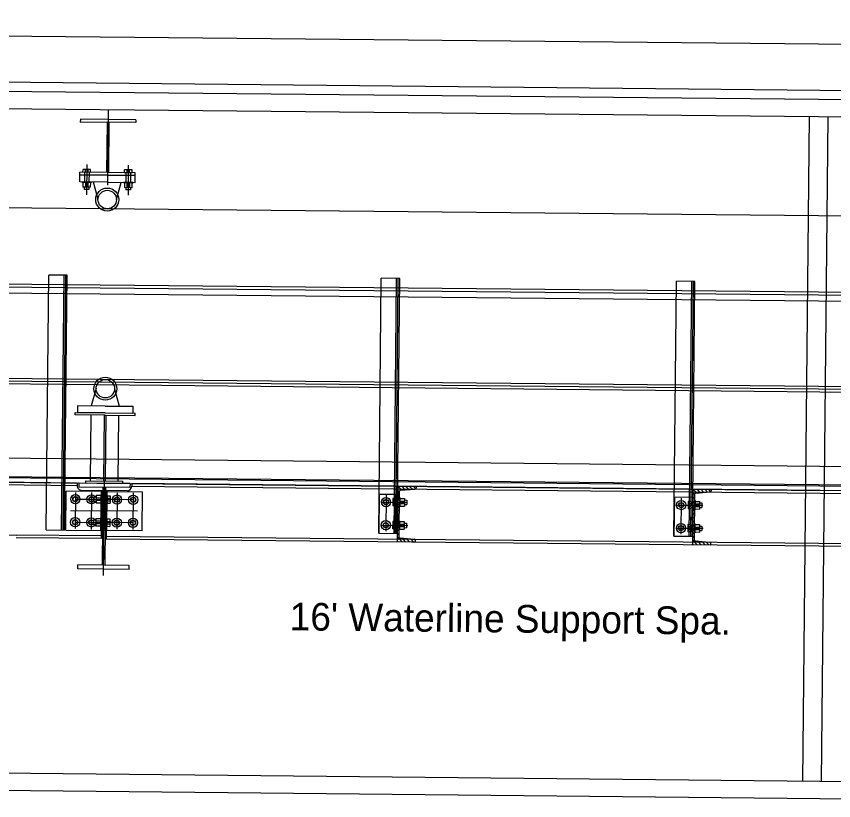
# Model space of a CAD drawing. Extents: x 632312 to 632885, y 378199 to 378534.
# Drawn here: x 632839.14 to 632853.91, y 378305.55 to 378319.72 of the extents above; entities that cross this region are included whole.
import ezdxf

# ---------------------------------------------------------------- set-up
doc = ezdxf.new("R2010")
doc.units = 0
doc.layers.add('SHT_Dimensions', color=7, linetype='Continuous')

msp = doc.modelspace()

# ---------------------------------------------------------------- linework, layer by layer
at = {"layer": 'SHT_Dimensions'}
for p, q in [((632803.483, 378319.72), (632858.169, 378319.176)), ((632803.475, 378318.886), (632858.055, 378318.344)), ((632803.473, 378318.72), (632858.195, 378318.176)), ((632803.47, 378318.407), (632858.281, 378317.862)), ((632840.801, 378318.035), (632840.788, 378316.671)), ((632853.468, 378317.91), (632853.348, 378305.911)), ((632840.3, 378317.862), (632840.299, 378317.811)), ((632841.299, 378317.801), (632840.299, 378317.811)), ((632841.3, 378317.852), (632840.3, 378317.862)), ((632840.783, 378317.807), (632840.774, 378316.899)), ((632840.815, 378317.806), (632840.806, 378316.899)), ((632841.3, 378317.852), (632841.299, 378317.801)), ((632853.801, 378317.907), (632853.681, 378305.907)), ((632840.416, 378317.042), (632840.411, 378316.495)), ((632841.166, 378317.034), (632841.161, 378316.488)), ((632841.29, 378316.894), (632840.29, 378316.904)), ((632840.29, 378316.854), (632840.29, 378316.904)), ((632840.347, 378316.903), (632840.348, 378316.955)), ((632840.483, 378316.902), (632840.347, 378316.903)), ((632840.483, 378316.954), (632840.348, 378316.955)), ((632840.373, 378316.903), (632840.372, 378316.728)), ((632840.393, 378316.903), (632840.393, 378316.955)), ((632840.438, 378316.902), (632840.438, 378316.955)), ((632840.457, 378316.902), (632840.455, 378316.727)), ((632840.483, 378316.902), (632840.483, 378316.954)), ((632841.097, 378316.896), (632841.098, 378316.948)), ((632841.233, 378316.895), (632841.097, 378316.896)), ((632841.233, 378316.947), (632841.098, 378316.948)), ((632841.123, 378316.896), (632841.122, 378316.72)), ((632841.143, 378316.895), (632841.143, 378316.948)), ((632841.188, 378316.895), (632841.188, 378316.947)), ((632841.207, 378316.895), (632841.205, 378316.719)), ((632841.233, 378316.895), (632841.233, 378316.947)), ((632841.29, 378316.844), (632841.29, 378316.894)), ((632840.288, 378316.729), (632840.29, 378316.854)), ((632840.788, 378316.724), (632840.288, 378316.729)), ((632840.79, 378316.849), (632840.29, 378316.854)), ((632841.29, 378316.844), (632840.29, 378316.854)), ((632840.79, 378316.849), (632841.29, 378316.844)), ((632841.288, 378316.719), (632841.29, 378316.844)), ((632858.298, 378316.07), (632803.452, 378316.616)), ((632840.33, 378316.728), (632840.33, 378316.718)), ((632840.497, 378316.726), (632840.33, 378316.728)), ((632840.497, 378316.716), (632840.33, 378316.718)), ((632840.346, 378316.718), (632840.345, 378316.634)), ((632840.48, 378316.633), (632840.345, 378316.634)), ((632840.371, 378316.634), (632840.37, 378316.592)), ((632840.454, 378316.591), (632840.37, 378316.592)), ((632840.391, 378316.717), (632840.39, 378316.634)), ((632840.436, 378316.717), (632840.435, 378316.633)), ((632840.454, 378316.633), (632840.454, 378316.591)), ((632840.481, 378316.716), (632840.48, 378316.633)), ((632840.497, 378316.726), (632840.497, 378316.716)), ((632840.619, 378316.413), (632840.538, 378316.726)), ((632840.788, 378316.724), (632841.288, 378316.719)), ((632840.952, 378316.409), (632841.038, 378316.721)), ((632841.08, 378316.721), (632841.08, 378316.71)), ((632841.247, 378316.719), (632841.08, 378316.721)), ((632841.247, 378316.709), (632841.08, 378316.71)), ((632841.096, 378316.71), (632841.095, 378316.627)), ((632841.23, 378316.625), (632841.095, 378316.627)), ((632841.121, 378316.626), (632841.12, 378316.585)), ((632841.204, 378316.584), (632841.12, 378316.585)), ((632841.141, 378316.71), (632841.14, 378316.626)), ((632841.186, 378316.709), (632841.185, 378316.626)), ((632841.204, 378316.626), (632841.204, 378316.584)), ((632841.231, 378316.709), (632841.23, 378316.625)), ((632841.247, 378316.719), (632841.247, 378316.709)), ((632803.438, 378315.189), (632857.879, 378314.647)), ((632803.439, 378315.241), (632857.859, 378314.7)), ((632858.496, 378314.527), (632803.437, 378315.074)), ((632839.683, 378310.443), (632839.729, 378315.046)), ((632840.062, 378315.043), (632839.729, 378315.046)), ((632839.959, 378310.44), (632840.005, 378315.044)), ((632839.99, 378310.439), (632840.036, 378315.043)), ((632840.016, 378310.439), (632840.062, 378315.043)), ((632845.69, 378310.385), (632845.736, 378314.989)), ((632846.069, 378314.986), (632845.736, 378314.989)), ((632845.966, 378310.382), (632846.012, 378314.986)), ((632845.997, 378310.382), (632846.043, 378314.986)), ((632846.023, 378310.382), (632846.069, 378314.986)), ((632851.023, 378310.332), (632851.069, 378314.936)), ((632851.402, 378314.933), (632851.069, 378314.936)), ((632851.299, 378310.329), (632851.345, 378314.933)), ((632851.33, 378310.329), (632851.376, 378314.933)), ((632851.357, 378310.329), (632851.402, 378314.933)), ((632803.421, 378313.491), (632857.782, 378312.95)), ((632857.708, 378312.993), (632803.422, 378313.532)), ((632803.421, 378313.439), (632857.788, 378312.898)), ((632840.585, 378312.996), (632840.498, 378312.685)), ((632840.918, 378312.993), (632840.998, 378312.68)), ((632840.248, 378312.687), (632840.247, 378312.562)), ((632840.748, 378312.682), (632840.248, 378312.687)), ((632840.748, 378312.682), (632841.248, 378312.677)), ((632841.248, 378312.677), (632841.247, 378312.552)), ((632840.205, 378312.521), (632840.205, 378312.562)), ((632840.205, 378312.562), (632841.289, 378312.552)), ((632840.747, 378312.515), (632840.205, 378312.521)), ((632840.747, 378312.557), (632840.247, 378312.562)), ((632840.485, 378311.33), (632840.497, 378312.518)), ((632840.722, 378311.328), (632840.734, 378312.516)), ((632840.747, 378312.557), (632841.247, 378312.552)), ((632840.759, 378312.515), (632840.747, 378311.328)), ((632840.747, 378312.515), (632841.288, 378312.51)), ((632840.985, 378311.325), (632840.996, 378312.513)), ((632841.288, 378312.51), (632841.289, 378312.552)), ((632803.407, 378312.095), (632857.654, 378311.556)), ((632803.404, 378311.762), (632857.65, 378311.222)), ((632803.404, 378311.741), (632857.65, 378311.201)), ((632803.403, 378311.657), (632853.734, 378311.157)), ((632840.241, 378311.291), (632824.315, 378311.45)), ((632840.24, 378311.243), (632824.332, 378311.401)), ((632840.241, 378311.291), (632840.24, 378311.243)), ((632840.272, 378311.291), (632840.271, 378311.218)), ((632841.197, 378311.282), (632840.272, 378311.291)), ((632840.401, 378311.29), (632840.401, 378311.331)), ((632840.401, 378311.331), (632841.068, 378311.325)), ((632840.485, 378311.33), (632840.985, 378311.325)), ((632840.718, 378309.624), (632840.735, 378311.338)), ((632841.068, 378311.283), (632841.068, 378311.325)), ((632841.197, 378311.282), (632841.196, 378311.209)), ((632857.643, 378311.118), (632841.228, 378311.281)), ((632841.228, 378311.281), (632841.228, 378311.233)), ((632840.037, 378310.439), (632840.044, 378311.147)), ((632840.711, 378311.141), (632840.044, 378311.147)), ((632840.21, 378311.123), (632840.204, 378310.468)), ((632841.196, 378311.209), (632840.271, 378311.218)), ((632840.323, 378311.159), (632840.69, 378311.155)), ((632840.502, 378311.12), (632840.495, 378310.449)), ((632840.672, 378310.433), (632840.679, 378311.141)), ((632840.681, 378310.287), (632840.69, 378311.155)), ((632840.697, 378309.809), (632840.711, 378311.214)), ((632840.703, 378310.432), (632840.711, 378311.141)), ((632840.756, 378311.214), (632840.742, 378309.809)), ((632840.748, 378310.432), (632840.755, 378311.14)), ((632840.755, 378311.14), (632841.422, 378311.134)), ((632840.776, 378311.155), (632840.767, 378310.286)), ((632841.143, 378311.151), (632840.776, 378311.155)), ((632840.779, 378310.432), (632840.786, 378311.14)), ((632841.228, 378311.233), (632857.678, 378311.07)), ((632841.415, 378310.425), (632841.422, 378311.134)), ((632846.032, 378311.234), (632846.022, 378310.234)), ((632846.062, 378311.134), (632846.031, 378311.165)), ((632846.032, 378311.234), (632846.365, 378311.23)), ((632846.101, 378311.166), (632846.034, 378311.234)), ((632846.062, 378311.144), (632846.054, 378310.323)), ((632846.067, 378311.233), (632846.067, 378311.232)), ((632846.083, 378311.164), (632846.344, 378311.183)), ((632846.167, 378311.17), (632846.105, 378311.233)), ((632846.232, 378311.175), (632846.176, 378311.232)), ((632846.298, 378311.179), (632846.247, 378311.231)), ((632846.359, 378311.188), (632846.317, 378311.231)), ((632846.365, 378311.23), (632846.365, 378311.203)), ((632851.365, 378311.181), (632851.355, 378310.181)), ((632851.365, 378311.181), (632851.698, 378311.177)), ((632851.434, 378311.113), (632851.367, 378311.181)), ((632851.4, 378311.18), (632851.4, 378311.179)), ((632851.416, 378311.111), (632851.677, 378311.13)), ((632851.5, 378311.117), (632851.438, 378311.18)), ((632851.565, 378311.122), (632851.509, 378311.179)), ((632851.631, 378311.126), (632851.58, 378311.178)), ((632851.692, 378311.135), (632851.65, 378311.178)), ((632851.698, 378311.177), (632851.698, 378311.15)), ((632840.209, 378311), (632840.501, 378310.997)), ((632840.501, 378310.997), (632840.731, 378310.995)), ((632840.543, 378311.038), (632840.542, 378310.955)), ((632840.585, 378311.038), (632840.543, 378311.038)), ((632840.585, 378311.064), (632840.583, 378310.928)), ((632840.668, 378311.018), (632840.584, 378311.019)), ((632840.667, 378310.973), (632840.584, 378310.974)), ((632840.668, 378311.063), (632840.585, 378311.064)), ((632840.668, 378311.079), (632840.667, 378310.912)), ((632840.679, 378311.078), (632840.668, 378311.079)), ((632840.679, 378311.078), (632840.677, 378310.912)), ((632840.785, 378311.036), (632840.678, 378311.037)), ((632840.962, 378310.992), (632840.731, 378310.995)), ((632840.786, 378311.062), (632840.784, 378310.926)), ((632840.785, 378311.017), (632840.837, 378311.016)), ((632840.785, 378310.972), (632840.837, 378310.971)), ((632840.786, 378311.062), (632840.838, 378311.061)), ((632840.838, 378311.061), (632840.836, 378310.926)), ((632840.963, 378311.115), (632840.957, 378310.459)), ((632841.254, 378310.989), (632840.962, 378310.992)), ((632841.255, 378311.112), (632841.248, 378310.453)), ((632845.697, 378311.093), (632845.69, 378310.385)), ((632845.697, 378311.093), (632846.031, 378311.09)), ((632845.822, 378311.069), (632845.816, 378310.421)), ((632845.946, 378311.013), (632845.945, 378310.877)), ((632845.998, 378311.012), (632845.946, 378311.013)), ((632845.992, 378310.382), (632845.999, 378311.09)), ((632845.998, 378311.012), (632845.997, 378310.877)), ((632845.998, 378310.986), (632846.06, 378310.986)), ((632846.023, 378310.382), (632846.031, 378311.09)), ((632846.06, 378310.993), (632846.03, 378311.024)), ((632846.061, 378311.064), (632846.031, 378311.095)), ((632846.061, 378311.027), (632846.059, 378310.861)), ((632846.061, 378311.027), (632846.071, 378311.027)), ((632846.071, 378311.027), (632846.069, 378310.861)), ((632846.071, 378311.012), (632846.154, 378311.011)), ((632846.154, 378311.011), (632846.153, 378310.875)), ((632846.154, 378310.985), (632846.196, 378310.984)), ((632846.196, 378310.984), (632846.195, 378310.901)), ((632851.03, 378311.04), (632851.023, 378310.332)), ((632851.03, 378311.04), (632851.364, 378311.037)), ((632851.155, 378311.016), (632851.149, 378310.368)), ((632851.325, 378310.329), (632851.332, 378311.037)), ((632851.357, 378310.329), (632851.364, 378311.037)), ((632851.393, 378310.94), (632851.363, 378310.971)), ((632851.395, 378311.081), (632851.364, 378311.112)), ((632851.394, 378311.01), (632851.364, 378311.042)), ((632851.395, 378311.091), (632851.387, 378310.27)), ((632851.394, 378310.974), (632851.392, 378310.808)), ((632851.394, 378310.974), (632851.404, 378310.974)), ((632851.404, 378310.974), (632851.403, 378310.808)), ((632840.584, 378310.954), (632840.542, 378310.955)), ((632840.667, 378310.928), (632840.583, 378310.928)), ((632840.677, 378310.912), (632840.667, 378310.912)), ((632840.785, 378310.952), (632840.677, 378310.953)), ((632840.784, 378310.926), (632840.836, 378310.926)), ((632845.737, 378310.947), (632846.212, 378310.942)), ((632845.997, 378310.877), (632845.945, 378310.877)), ((632845.998, 378310.967), (632845.946, 378310.968)), ((632845.998, 378310.922), (632845.946, 378310.923)), ((632845.997, 378310.903), (632846.059, 378310.902)), ((632846.059, 378310.851), (632846.028, 378310.883)), ((632846.06, 378310.922), (632846.029, 378310.953)), ((632846.059, 378310.861), (632846.069, 378310.861)), ((632846.07, 378310.921), (632846.153, 378310.921)), ((632846.07, 378310.876), (632846.153, 378310.875)), ((632846.071, 378310.966), (632846.154, 378310.966)), ((632846.153, 378310.901), (632846.195, 378310.901)), ((632851.071, 378310.894), (632851.545, 378310.889)), ((632851.279, 378310.96), (632851.278, 378310.824)), ((632851.33, 378310.824), (632851.278, 378310.824)), ((632851.332, 378310.959), (632851.279, 378310.96)), ((632851.331, 378310.914), (632851.279, 378310.915)), ((632851.331, 378310.869), (632851.279, 378310.87)), ((632851.332, 378310.959), (632851.33, 378310.824)), ((632851.33, 378310.85), (632851.393, 378310.849)), ((632851.331, 378310.933), (632851.393, 378310.933)), ((632851.393, 378310.869), (632851.362, 378310.9)), ((632851.392, 378310.798), (632851.362, 378310.829)), ((632851.403, 378310.868), (632851.486, 378310.867)), ((632851.403, 378310.823), (632851.486, 378310.822)), ((632851.404, 378310.959), (632851.487, 378310.958)), ((632851.404, 378310.913), (632851.487, 378310.913)), ((632851.487, 378310.958), (632851.486, 378310.822)), ((632851.486, 378310.848), (632851.528, 378310.848)), ((632851.487, 378310.932), (632851.529, 378310.931)), ((632851.529, 378310.931), (632851.528, 378310.848)), ((632841.335, 378310.78), (632840.124, 378310.792)), ((632846.058, 378310.71), (632846.027, 378310.741)), ((632846.058, 378310.781), (632846.028, 378310.812)), ((632851.391, 378310.657), (632851.36, 378310.688)), ((632851.391, 378310.728), (632851.361, 378310.759)), ((632851.392, 378310.808), (632851.403, 378310.808)), ((632840.205, 378310.583), (632840.497, 378310.58)), ((632840.497, 378310.58), (632840.727, 378310.578)), ((632840.539, 378310.622), (632840.538, 378310.538)), ((632840.58, 378310.538), (632840.538, 378310.538)), ((632840.58, 378310.621), (632840.539, 378310.622)), ((632840.581, 378310.647), (632840.579, 378310.512)), ((632840.664, 378310.601), (632840.58, 378310.602)), ((632840.663, 378310.556), (632840.58, 378310.557)), ((632840.664, 378310.646), (632840.581, 378310.647)), ((632840.664, 378310.662), (632840.662, 378310.495)), ((632840.675, 378310.662), (632840.664, 378310.662)), ((632840.675, 378310.662), (632840.673, 378310.495)), ((632840.78, 378310.536), (632840.673, 378310.537)), ((632840.781, 378310.619), (632840.674, 378310.62)), ((632840.958, 378310.576), (632840.727, 378310.578)), ((632840.781, 378310.645), (632840.78, 378310.51)), ((632840.781, 378310.645), (632840.834, 378310.645)), ((632840.781, 378310.6), (632840.833, 378310.599)), ((632840.781, 378310.555), (632840.833, 378310.554)), ((632840.834, 378310.645), (632840.832, 378310.509)), ((632841.25, 378310.573), (632840.958, 378310.576)), ((632845.733, 378310.531), (632846.215, 378310.526)), ((632845.942, 378310.596), (632845.941, 378310.461)), ((632845.994, 378310.596), (632845.942, 378310.596)), ((632845.994, 378310.551), (632845.942, 378310.551)), ((632845.994, 378310.596), (632845.993, 378310.46)), ((632845.994, 378310.57), (632846.056, 378310.569)), ((632846.055, 378310.498), (632846.025, 378310.529)), ((632846.057, 378310.639), (632846.026, 378310.67)), ((632846.056, 378310.569), (632846.026, 378310.6)), ((632846.057, 378310.611), (632846.055, 378310.444)), ((632846.057, 378310.611), (632846.067, 378310.611)), ((632846.067, 378310.611), (632846.065, 378310.444)), ((632846.066, 378310.55), (632846.15, 378310.549)), ((632846.067, 378310.595), (632846.15, 378310.594)), ((632846.15, 378310.594), (632846.149, 378310.459)), ((632846.15, 378310.568), (632846.192, 378310.568)), ((632846.192, 378310.568), (632846.191, 378310.484)), ((632851.275, 378310.543), (632851.274, 378310.408)), ((632851.327, 378310.543), (632851.275, 378310.543)), ((632851.327, 378310.543), (632851.326, 378310.407)), ((632851.39, 378310.586), (632851.359, 378310.617)), ((632851.389, 378310.516), (632851.359, 378310.547)), ((632851.39, 378310.558), (632851.388, 378310.391)), ((632851.39, 378310.558), (632851.4, 378310.558)), ((632851.4, 378310.558), (632851.398, 378310.391)), ((632851.4, 378310.542), (632851.483, 378310.541)), ((632851.483, 378310.541), (632851.482, 378310.406)), ((632822.769, 378310.513), (632839.144, 378310.35)), ((632839.683, 378310.443), (632840.016, 378310.439)), ((632840.037, 378310.439), (632840.703, 378310.432)), ((632840.663, 378310.511), (632840.579, 378310.512)), ((632840.673, 378310.495), (632840.662, 378310.495)), ((632841.415, 378310.425), (632840.748, 378310.432)), ((632840.78, 378310.51), (632840.832, 378310.509)), ((632845.69, 378310.385), (632846.023, 378310.382)), ((632845.69, 378310.385), (632846.023, 378310.382)), ((632845.993, 378310.505), (632845.941, 378310.506)), ((632845.993, 378310.46), (632845.941, 378310.461)), ((632845.993, 378310.486), (632846.055, 378310.486)), ((632846.055, 378310.427), (632846.024, 378310.458)), ((632846.054, 378310.356), (632846.024, 378310.388)), ((632846.055, 378310.444), (632846.065, 378310.444)), ((632846.065, 378310.46), (632846.149, 378310.459)), ((632846.066, 378310.505), (632846.149, 378310.504)), ((632846.149, 378310.485), (632846.191, 378310.484)), ((632851.066, 378310.478), (632851.548, 378310.473)), ((632851.327, 378310.452), (632851.274, 378310.453)), ((632851.326, 378310.407), (632851.274, 378310.408)), ((632851.327, 378310.498), (632851.275, 378310.498)), ((632851.326, 378310.433), (632851.388, 378310.433)), ((632851.327, 378310.517), (632851.389, 378310.516)), ((632851.388, 378310.374), (632851.357, 378310.405)), ((632851.389, 378310.445), (632851.358, 378310.476)), ((632851.388, 378310.391), (632851.398, 378310.391)), ((632851.399, 378310.497), (632851.483, 378310.496)), ((632851.399, 378310.452), (632851.482, 378310.451)), ((632851.399, 378310.407), (632851.482, 378310.406)), ((632851.482, 378310.432), (632851.524, 378310.431)), ((632851.483, 378310.515), (632851.525, 378310.515)), ((632851.525, 378310.515), (632851.524, 378310.431)), ((632840.681, 378310.287), (632839.143, 378310.302)), ((632840.682, 378310.335), (632839.144, 378310.35)), ((632840.767, 378310.286), (632857.662, 378310.118)), ((632840.768, 378310.334), (632857.657, 378310.166)), ((632846.035, 378310.234), (632846.022, 378310.246)), ((632846.025, 378310.234), (632846.022, 378310.237)), ((632846.022, 378310.234), (632846.355, 378310.23)), ((632846.022, 378310.234), (632846.355, 378310.23)), ((632846.105, 378310.233), (632846.023, 378310.317)), ((632846.074, 378310.302), (632846.335, 378310.278)), ((632846.176, 378310.232), (632846.111, 378310.299)), ((632846.247, 378310.231), (632846.188, 378310.292)), ((632846.317, 378310.231), (632846.264, 378310.285)), ((632846.355, 378310.264), (632846.342, 378310.277)), ((632846.355, 378310.23), (632846.356, 378310.257)), ((632851.023, 378310.332), (632851.357, 378310.329)), ((632851.023, 378310.332), (632851.357, 378310.329)), ((632851.438, 378310.18), (632851.356, 378310.264)), ((632851.387, 378310.303), (632851.357, 378310.335)), ((632851.407, 378310.249), (632851.668, 378310.225)), ((632851.509, 378310.179), (632851.444, 378310.246)), ((632851.58, 378310.178), (632851.521, 378310.239)), ((632851.368, 378310.18), (632851.355, 378310.193)), ((632851.358, 378310.181), (632851.355, 378310.184)), ((632851.355, 378310.181), (632851.688, 378310.177)), ((632851.355, 378310.181), (632851.688, 378310.177)), ((632851.65, 378310.178), (632851.597, 378310.232)), ((632851.688, 378310.211), (632851.675, 378310.224)), ((632851.688, 378310.177), (632851.689, 378310.204)), ((632840.256, 378309.741), (632840.257, 378309.813)), ((632841.182, 378309.804), (632840.257, 378309.813)), ((632841.181, 378309.732), (632841.182, 378309.804)), ((632841.181, 378309.732), (632840.256, 378309.741)), ((632803.351, 378306.408), (632857.672, 378305.868)), ((632803.348, 378306.095), (632857.7, 378305.555))]:
    msp.add_line(p, q, dxfattribs=at)
for centre, radius in [((632840.785, 378316.411), 0.208), ((632840.785, 378316.411), 0.167), ((632840.751, 378312.995), 0.208), ((632840.751, 378312.995), 0.167), ((632840.209, 378311), 0.0833), ((632840.209, 378311), 0.0469), ((632840.209, 378311), 0.0417), ((632840.501, 378310.997), 0.0833), ((632840.501, 378310.997), 0.0469), ((632840.501, 378310.997), 0.0417), ((632840.962, 378310.992), 0.0833), ((632840.962, 378310.992), 0.0469), ((632840.962, 378310.992), 0.0417), ((632841.254, 378310.989), 0.0833), ((632841.254, 378310.989), 0.0469), ((632841.254, 378310.989), 0.0417), ((632845.821, 378310.946), 0.0833), ((632845.821, 378310.946), 0.0469), ((632845.821, 378310.946), 0.0417), ((632851.154, 378310.893), 0.0833), ((632851.154, 378310.893), 0.0469), ((632851.154, 378310.893), 0.0417), ((632840.205, 378310.583), 0.0833), ((632840.205, 378310.583), 0.0469), ((632840.205, 378310.583), 0.0417), ((632840.497, 378310.58), 0.0833), ((632840.497, 378310.58), 0.0469), ((632840.497, 378310.58), 0.0417), ((632840.958, 378310.576), 0.0833), ((632840.958, 378310.576), 0.0469), ((632840.958, 378310.576), 0.0417), ((632841.25, 378310.573), 0.0833), ((632841.25, 378310.573), 0.0469), ((632841.25, 378310.573), 0.0417), ((632845.817, 378310.53), 0.0833), ((632845.817, 378310.53), 0.0469), ((632845.817, 378310.53), 0.0417), ((632851.15, 378310.477), 0.0833), ((632851.15, 378310.477), 0.0469), ((632851.15, 378310.477), 0.0417)]:
    msp.add_circle(centre, radius, dxfattribs=at)
for centre, radius, start, end in [((632840.323, 378311.242), 0.0833, 179.4304, 269.4304), ((632841.144, 378311.234), 0.0833, 269.4304, 359.4304), ((632846.083, 378311.144), 0.0208, 89.4304, 179.4304), ((632846.344, 378311.203), 0.0208, 269.4304, 359.4388), ((632851.677, 378311.15), 0.0208, 269.4304, 359.4388), ((632851.416, 378311.09), 0.0208, 89.4304, 179.4304), ((632846.075, 378310.323), 0.0208, 179.4304, 269.4304), ((632846.335, 378310.258), 0.0208, 359.4304, 89.4304), ((632851.408, 378310.27), 0.0208, 179.4304, 269.4304), ((632851.668, 378310.205), 0.0208, 359.4304, 89.4304)]:
    msp.add_arc(centre, radius, start, end, dxfattribs=at)

# ---------------------------------------------------------------- texts
msp.add_text("16' Waterline Support Spa.", height=0.5, rotation=359.4304, dxfattribs=at).set_placement((632844.08, 378308.631))

doc.saveas('drawing.dxf')
